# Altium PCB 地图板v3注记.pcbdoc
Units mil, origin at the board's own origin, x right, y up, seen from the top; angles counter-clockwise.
Board outline 3346.45 x 2125.98 mil, 2 copper layers (Top Layer, Bottom Layer); 72 components, 11 nets, 236 pads, 2 vias.
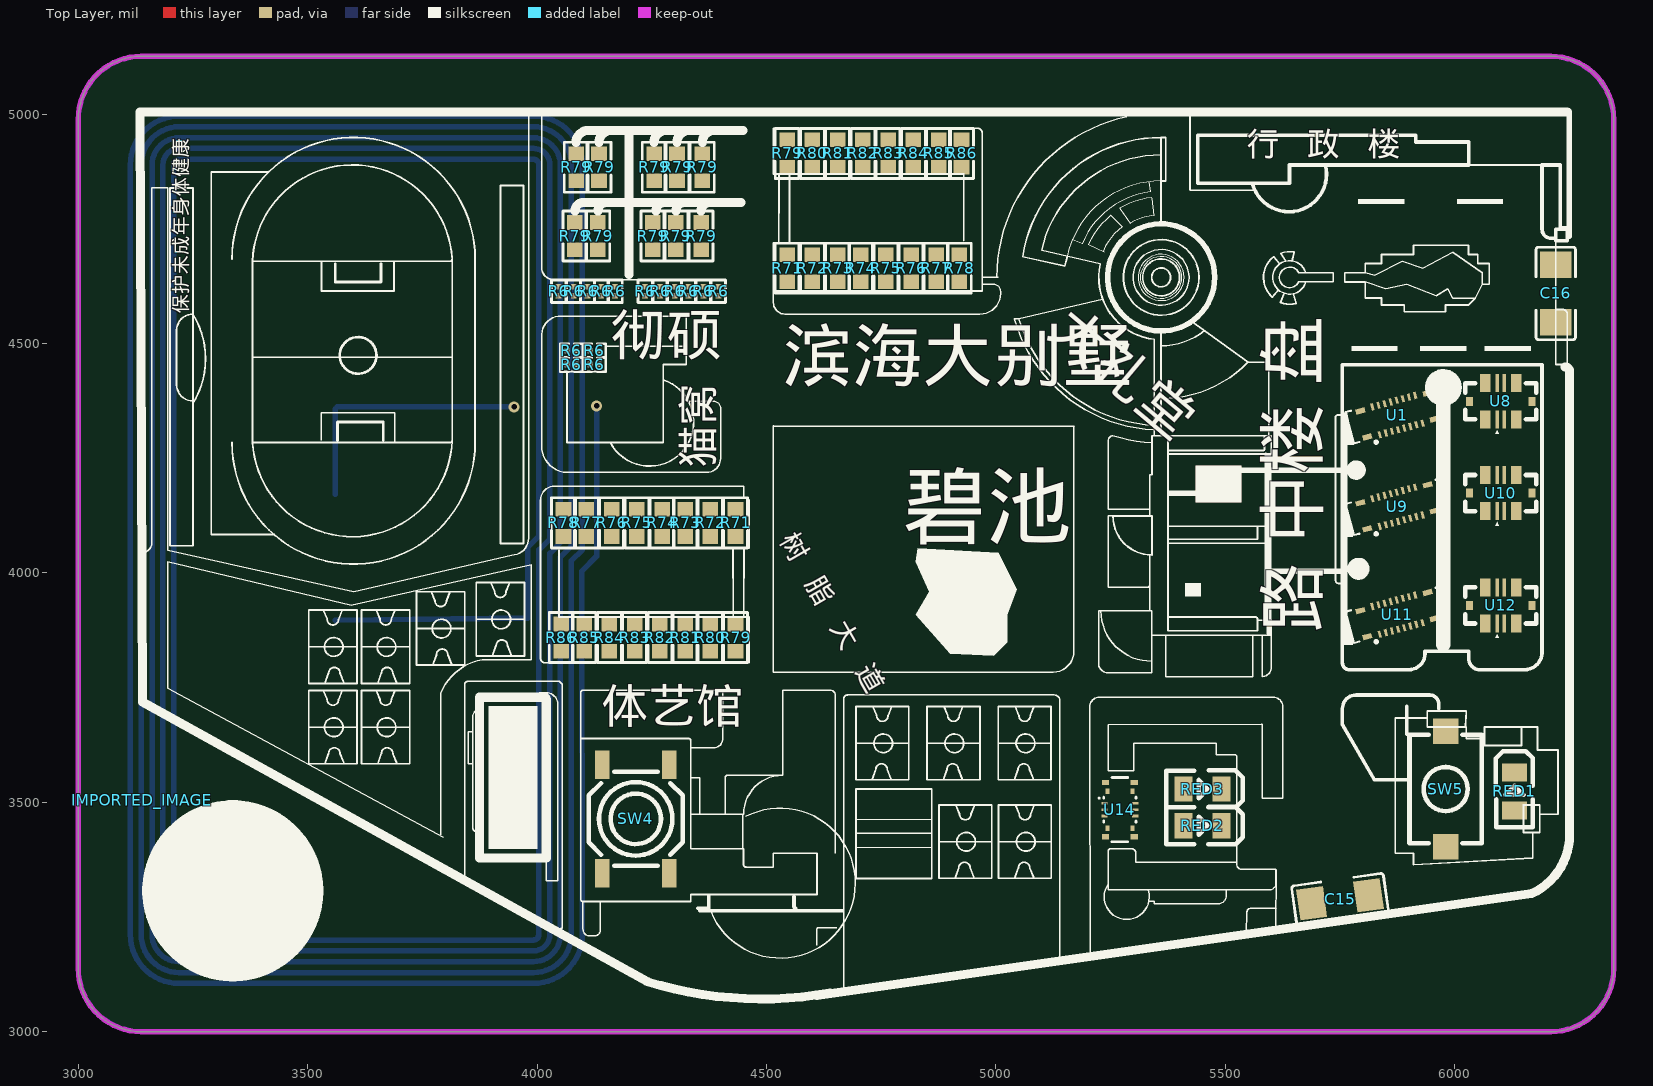
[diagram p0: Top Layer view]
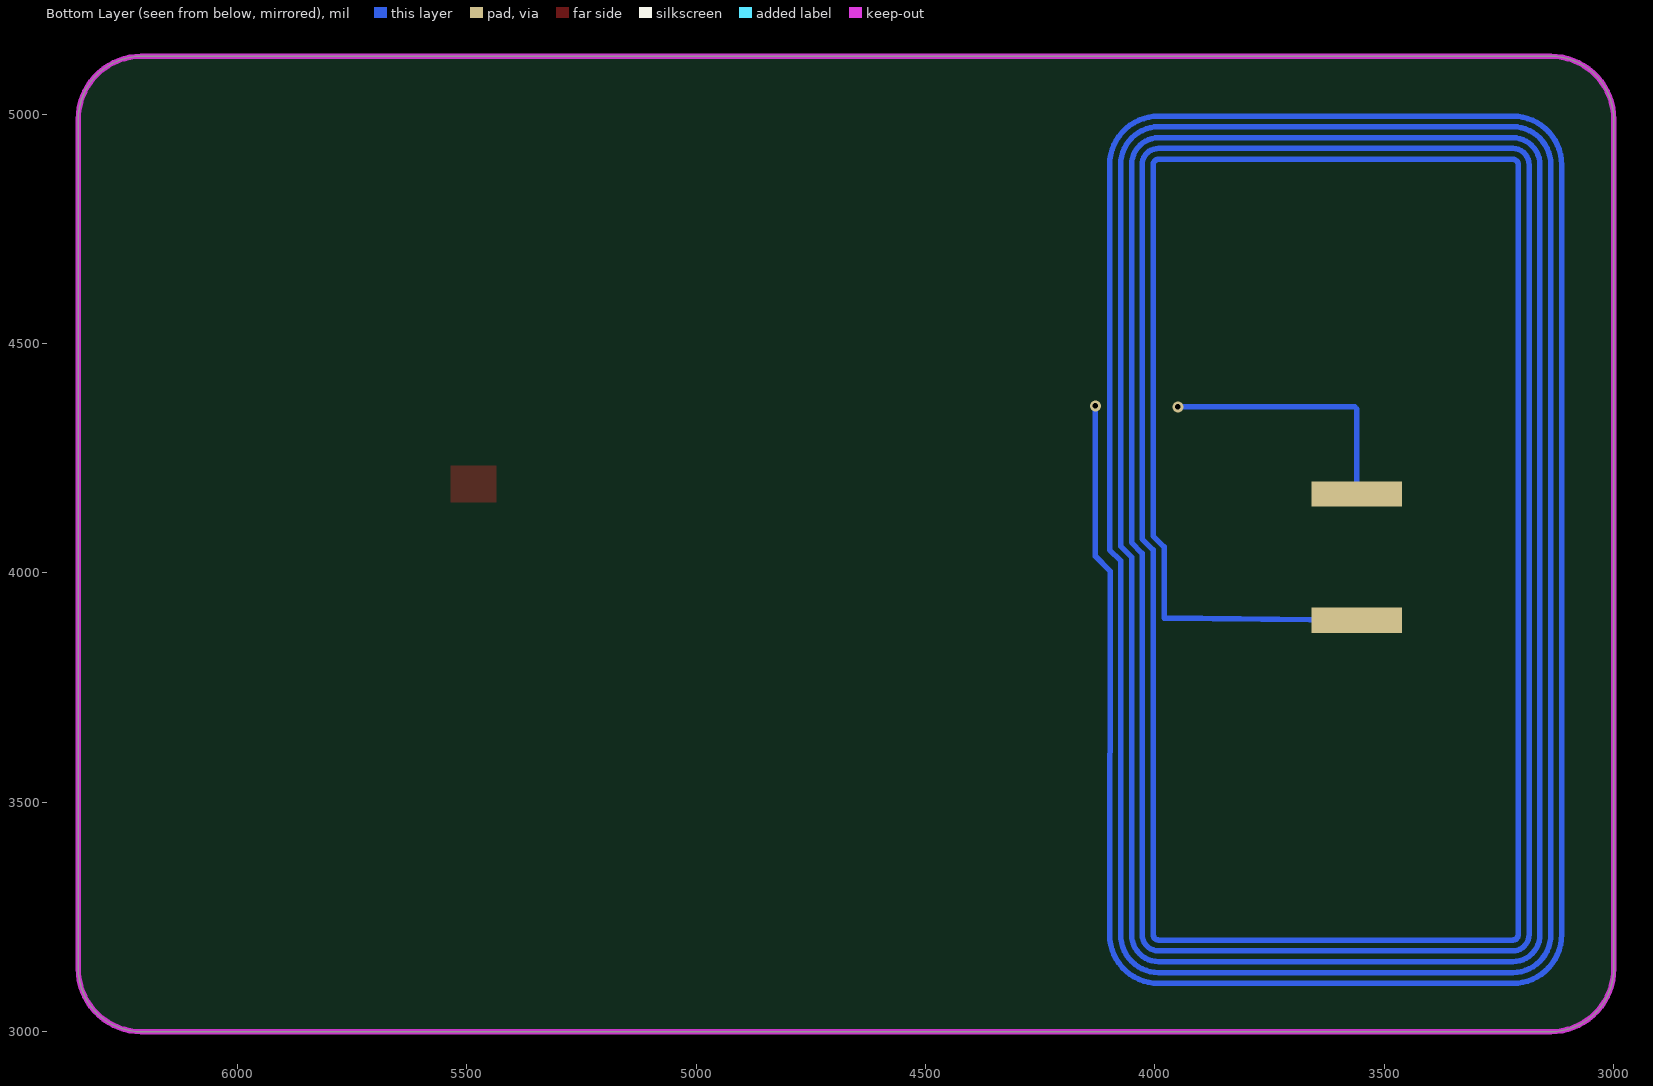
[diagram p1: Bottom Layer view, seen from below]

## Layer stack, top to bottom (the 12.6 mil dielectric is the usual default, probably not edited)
Top Layer: signal copper (thickness not stored)
Dielectric: dielectric 12.6, FR-4, Dk 4.8
Bottom Layer: signal copper (thickness not stored)

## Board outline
3000,4988.19 cw(c3137.8,4988.19) 3137.8,5125.98 6208.65,5125.98 cw(c6208.65,4988.19) 6346.45,4988.18 6346.45,3137.8 cw(c6208.65,3137.8) 6208.66,3000 3137.8,3000 cw(c3137.8,3137.8) 3000,3137.8 3000,4988.18

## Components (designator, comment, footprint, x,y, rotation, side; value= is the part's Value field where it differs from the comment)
C15 "0.1u" C1206 5750,3288.98 r8 top
C16 "0.1u" C1206 6220,4608.98 r90 top
IMPORTED_IMAGE "IMPORTED_IMAGE" IMPORTED_IMAGE 3140,3503.98 r0 top
R6 "1k" R0201 4125,4453.98 r0 top
R6 "1k" R0201 4125,4483.98 r0 top
R6 "1k" R0201 4075,4453.98 r0 top
R6 "1k" R0201 4075,4483.98 r0 top
R6 "1k" R0201 4046.87,4613.98 r270 top
R6 "1k" R0201 4080,4613.98 r270 top
R6 "1k" R0201 4110,4613.98 r270 top
R6 "1k" R0201 4140,4613.98 r270 top
R6 "1k" R0201 4170,4613.98 r270 top
R6 "1k" R0201 4235.53,4613.98 r270 top
R6 "1k" R0201 4267.97,4613.98 r270 top
R6 "1k" R0201 4300,4613.98 r270 top
R6 "1k" R0201 4329.96,4613.98 r270 top
R6 "1k" R0201 4362.39,4613.98 r270 top
R6 "1k" R0201 4395,4613.98 r270 top
R71 "1k" R0603 4545,4663.98 r90 top
R71 "1k" R0603 4432.5,4108.98 r270 top
R72 "1k" R0603 4600,4663.98 r90 top
R72 "1k" R0603 4377.5,4108.98 r270 top
R73 "1k" R0603 4655,4663.98 r90 top
R73 "1k" R0603 4322.5,4108.98 r270 top
R74 "1k" R0603 4705,4663.98 r90 top
R74 "1k" R0603 4272.5,4108.98 r270 top
R75 "1k" R0603 4760,4663.98 r90 top
R75 "1k" R0603 4217.5,4108.98 r270 top
R76 "1k" R0603 4815,4663.98 r90 top
R76 "1k" R0603 4162.5,4108.98 r270 top
R77 "1k" R0603 4870,4663.98 r90 top
R77 "1k" R0603 4107.5,4108.98 r270 top
R78 "1k" R0603 4920,4663.98 r90 top
R78 "1k" R0603 4057.5,4108.98 r270 top
R79 "1k" R0603 4545,4913.98 r90 top
R79 "1k" R0603 4432.5,3858.98 r270 top
R79 "1k" R0603 4085,4883.98 r90 top
R79 "1k" R0603 4135,4883.98 r90 top
R79 "1k" R0603 4255,4883.98 r90 top
R79 "1k" R0603 4305,4883.98 r90 top
R79 "1k" R0603 4360,4883.98 r90 top
R79 "1k" R0603 4082.5,4733.98 r90 top
R79 "1k" R0603 4132.5,4733.98 r90 top
R79 "1k" R0603 4252.5,4733.98 r90 top
R79 "1k" R0603 4357.5,4733.98 r90 top
R79 "1k" R0603 4302.5,4733.98 r90 top
R80 "1k" R0603 4600,4913.98 r90 top
R80 "1k" R0603 4377.5,3858.98 r270 top
R81 "1k" R0603 4655,4913.98 r90 top
R81 "1k" R0603 4322.5,3858.98 r270 top
R82 "1k" R0603 4710,4913.98 r90 top
R82 "1k" R0603 4267.5,3858.98 r270 top
R83 "1k" R0603 4765,4913.98 r90 top
R83 "1k" R0603 4212.5,3858.98 r270 top
R84 "1k" R0603 4820,4913.98 r90 top
R84 "1k" R0603 4157.5,3858.98 r270 top
R85 "1k" R0603 4875,4913.98 r90 top
R85 "1k" R0603 4102.5,3858.98 r270 top
R86 "1k" R0603 4925,4913.98 r90 top
R86 "1k" R0603 4052.5,3858.98 r270 top
RED1 "LED0805-R-RD" LED0805-R-RD 6130,3523.98 r270 top
RED2 "LED0805-R-RD" LED0805-R-RD 5450,3448.98 r180 top
RED3 "LED0805-R-RD" LED0805-R-RD 5450,3528.98 r180 top
SW4 "SW-SMD_4P-L5.2-W5.2-P3.70-LS6.4" SW-SMD_4P-L5.2-W5.2-P3.70-LS6.4 4215,3463.98 r90 top
SW5 "YTS1C0192ABG00" SW-SMD_L6.0-W4.0-LS7.2 5980,3528.98 r90 top
U1 "CONN-SMD_BM28B0.6-16DS-2-0.35V-51" CONN-SMD_BM28B0.6-16DS-2-0.35V-51 5875,4343.98 r15 top
U8 "CONN-SMD_BM25-4P-2-V-51" CONN-SMD_BM25-4P-2-V-51 6100,4373.98 r0 top
U9 "CONN-SMD_BM28B0.6-16DS-2-0.35V-51" CONN-SMD_BM28B0.6-16DS-2-0.35V-51 5875,4143.98 r15 top
U10 "CONN-SMD_BM25-4P-2-V-51" CONN-SMD_BM25-4P-2-V-51 6100,4173.98 r0 top
U11 "CONN-SMD_BM28B0.6-16DS-2-0.35V-51" CONN-SMD_BM28B0.6-16DS-2-0.35V-51 5875,3908.98 r15 top
U12 "CONN-SMD_BM25-4P-2-V-51" CONN-SMD_BM25-4P-2-V-51 6100,3928.98 r0 top
U14 "CONN-SMD_AXG106144" CONN-SMD_AXG106144 5270,3483.98 r270 top

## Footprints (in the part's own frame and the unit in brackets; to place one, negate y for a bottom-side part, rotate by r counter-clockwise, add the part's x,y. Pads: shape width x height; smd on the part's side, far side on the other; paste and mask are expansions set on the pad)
C1206 [mm]
  rect 1.485x1.728 smd paste-100 mask+0.051: 1(-1.593,0) 2(1.593,0)
  silkscreen extent -2.56,-1.09 2.56,1.09
CONN-SMD_AXG106144 [mm]
  rect 0.15x0.35 smd paste+0 mask+0.05: 1(-0.35,-0.845) 2(-0.35,0.845) 3(0,-0.845) 4(0,0.845) 5(0.35,-0.845) 6(0.35,0.845)
  rect 0.3x0.22 smd paste+0 mask+0.05: 7(1.03,0.69) 8(1.03,-0.69) 11(-1.03,-0.69) 12(-1.03,0.69)
  rect 0.28x0.4 smd paste+0 mask+0.05: 9(1.5,0.8) 10(1.5,-0.8) 13(-1.5,-0.8) 14(-1.5,0.8)
  silkscreen extent -1.78,-1.17 1.78,0.89
CONN-SMD_BM25-4P-2-V-51 [mm]
  rect 0.2x1 smd: 1(-0.2,-1) 2(-0.2,1) 3(0.2,-1) 4(0.2,1)
  rect 0.58x1 smd: 5(0.85,-1) 6(0.85,1) 7(-0.85,1) 8(-0.85,-1)
  rect 0.38x0.5 smd: 9(-1.735,0) 10(1.735,0)
  silkscreen extent -1.97,-1.8 1.97,1
CONN-SMD_BM28B0.6-16DS-2-0.35V-51 [mm]
  rect 0.15x0.41 smd: 1(-1.225,-0.795) 2(-0.875,-0.795) 3(-0.525,-0.795) 4(-0.175,-0.795) 5(0.175,-0.795) 6(0.525,-0.795) 7(0.875,-0.795) 8(1.225,-0.795) 9(1.225,0.795) 10(0.875,0.795) 11(0.525,0.795) 12(0.175,0.795) 13(-0.175,0.795) 14(-0.525,0.795) 15(-0.875,0.795) 16(-1.225,0.795)
  rect 0.53x0.31 smd: 17(-1.93,0.745) 18(-1.93,-0.745) 19(1.93,-0.745) 20(1.93,0.745)
  silkscreen extent -2.73,-1.22 2.67,0.9
IMPORTED_IMAGE [mil]
  silkscreen extent 0,-394 394,0
LED0805-R-RD [mm]
  rect 1x1.4 smd: 1(1.05,0) 2(-1.05,0)
  silkscreen extent -2.22,-1.04 1.99,1.01
R0201 [mil]
  rect 11.93x12.76 smd paste-3937.01 mask+2: 1(-9.51,0) 2(9.51,0)
  silkscreen extent -24,-15 24,15
R0603 [mil]
  rect 31.75x34.02 smd paste-3937.01 mask+2: 1(-29.66,0) 2(29.66,0)
  silkscreen extent -55,-26 55,26
SW-SMD_4P-L5.2-W5.2-P3.70-LS6.4 [mm]
  rect 1.58x0.8 smd: 1(-3,1.85) 2(3,1.85) 3(-3,-1.85) 4(3,-1.85)
  silkscreen extent -2.6,-2.6 2.6,2.6
SW-SMD_L6.0-W4.0-LS7.2 [mm]
  rect 1.4x1.4 smd paste+0 mask+0.05: 1(-3.2,0) 2(3.2,0)
  silkscreen extent -3,-2 3,2

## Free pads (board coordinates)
  rect 196.85x55.12 smd far side paste+0 mask-196.85: 11(3560,3896.69) 11(3560,4171.69)

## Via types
v1: diameter 24, hole 12, Top Layer to Bottom Layer, 2 vias

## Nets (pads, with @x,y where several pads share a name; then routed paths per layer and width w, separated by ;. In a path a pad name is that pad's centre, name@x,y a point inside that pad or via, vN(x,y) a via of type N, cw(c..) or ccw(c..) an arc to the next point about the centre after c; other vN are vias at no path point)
C5_1: C15.1 C16.1
C5_2: C15.2 C16.2
R3_1: R71.1 R72.1 R73.1 R74.1 R75.1 R76.1 R77.1 R78.1 R79.1 R80.1 R81.1 R82.1 R83.1 R84.1 R85.1 R86.1
R3_2: R71.2 R72.2 R73.2 R74.2 R75.2 R76.2 R77.2 R78.2 R79.2 R80.2 R81.2 R82.2 R83.2 R84.2 R85.2 R86.2
R6_1: R6.1
R6_2: R6.2
S$48780: pad.11@3560,3896.69 | length 1417.4
  Bottom Layer w12: pad.11@3560,3896.69 3980,3901.69 3980,4056.69 4003.8,4080.49 4003.8,4889.19
S$48796: pad.11@3560,4171.69 | length 950.6
  Bottom Layer w12.01: pad.11@3560,4171.69 3560,4356.69 3565,4361.69 v1(3950,4361.69) ; 4097.45,4003.93 4130,4036.47 v1(4130,4363.98)
SW1_1: SW5.1
SW1_2: SW5.2
"": RED1.1 RED1.2 RED2.1 RED2.2 RED3.1 RED3.2 SW4.1 SW4.2 SW4.3 SW4.4 U1.1 U1.2 U1.3 U1.4 U1.5 U1.6 U1.7 U1.8 U1.9 U1.10 U1.11 U1.12 U1.13 U1.14 U1.15 U1.16 U1.17 U1.18 U1.19 U1.20 U8.1 U8.2 U8.3 U8.4 U8.5 U8.6 U8.7 U8.8 U8.9 U8.10 U9.1 U9.2 U9.3 U9.4 U9.5 U9.6 U9.7 U9.8 U9.9 U9.10 U9.11 U9.12 U9.13 U9.14 U9.15 U9.16 U9.17 U9.18 U9.19 U9.20 U10.1 U10.2 U10.3 U10.4 U10.5 U10.6 U10.7 U10.8 U10.9 U10.10 U11.1 U11.2 U11.3 U11.4 U11.5 U11.6 U11.7 U11.8 U11.9 U11.10 U11.11 U11.12 U11.13 U11.14 U11.15 U11.16 U11.17 U11.18 U11.19 U11.20 U12.1 U12.2 U12.3 U12.4 U12.5 U12.6 U12.7 U12.8 U12.9 U12.10 U14.1 U14.2 U14.3 U14.4 U14.5 U14.6 U14.7 U14.8 U14.9 U14.10 U14.11 U14.12 U14.13 U14.14 | length 25507.2
  Bottom Layer w12: 3113.7,4889.27 cw(c3219.85,4889.13) 3220,4995.27 ; 3113.7,4889.27 3113.7,3211.69 ccw(c3220,3211.69) 3220,3105.39 3991.83,3105.39 ccw(c3992.18,3212.04) 4098.83,3211.69 4097.44,4003.95 ; 3137.32,4889.27 cw(c3220.16,4889.44) 3220,4972.27 ; 3137.32,4889.27 3137.32,3211.69 ccw(c3220,3211.69) 3220,3129.02 3991.83,3129.02 ccw(c3991.99,3211.85) 4074.83,3211.69 4074.83,4026.65 4098.83,4050.28 4098.83,4889.27 ccw(c3992.33,4888.77) 3991.83,4995.28 3220,4995.28 ; 3184.57,4889.27 cw(c3220.28,4889.56) 3220,4925.27 ; 3184.57,4889.27 3184.57,3211.69 ccw(c3220,3211.69) 3220,3176.26 3991.83,3176.26 ccw(c3992.11,3211.98) 4027.83,3211.69 4027.83,4042.4 4050.83,4066.28 4050.83,4889.27 ccw(c3991.83,4889.27) 3991.83,4948.27 3220,4948.28 ; 3220,4925.28 3991.83,4925.28 cw(c3991.83,4889.27) 4027.83,4889.27 4027.83,4074.28 4003.83,4050.28 4003.83,3211.69 cw(c3991.92,3211.79) 3991.83,3199.88 3220,3199.88 cw(c3220,3211.69) 3208.19,3211.69 3208.19,4889.27 cw(c3220.09,4889.37) 3220,4901.28 3991.83,4901.28 cw(c3991.83,4889.27) 4003.83,4889.27 ; 3220,4948.27 ccw(c3219.97,4889.25) 3160.95,4889.28 3160.95,3211.69 ccw(c3220,3211.69) 3220,3152.64 3991.83,3152.64 ccw(c3991.8,3211.66) 4050.83,3211.69 4050.83,4034.53 4074.83,4058.28 4074.83,4889.27 ccw(c3991.83,4889.27) 3991.83,4972.27 3220,4972.27

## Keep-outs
Board Outline Layer:
  the board outline again, w11.81

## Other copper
Top Layer:
  region net "": 5535,4153.98 5535,4233.98 5435,4233.98 5435,4153.98

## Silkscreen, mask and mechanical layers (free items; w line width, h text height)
Top Silkscreen Layer:
  drawing of 750 lines, arcs and shapes, not listed
  text "行   政   楼" at 5545.86,4908.85 h53.52
  text "保护未成年身体健康" at 3239.24,4564.48 h31.22 r90
  text "大礼堂" at 5110.66,4521.52 h89.2 r320
  text "彻硕" at 4159.88,4475.44 h89.2
  text "滨海大别墅" at 4535.68,4419.55 h111.5
  text "猫窝" at 4382.66,4228.89 h66.9 r90
  text "碧池" at 4794.82,4079.06 h135.94
  text "树   脂   大   道" at 4527.71,4072.09 h44.6 r300
  text "路 中楼 盘" at 5699.43,3869.94 h111.5 r90
  text "体艺馆" at 4140.09,3672.97 h75.82
Bottom Solder Mask Layer:
  region net "": 3465,4141.69 3655,4141.69 3655,4196.69 3465,4196.69
  region net "": 3465,3871.69 3655,3871.69 3655,3926.69 3465,3926.69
